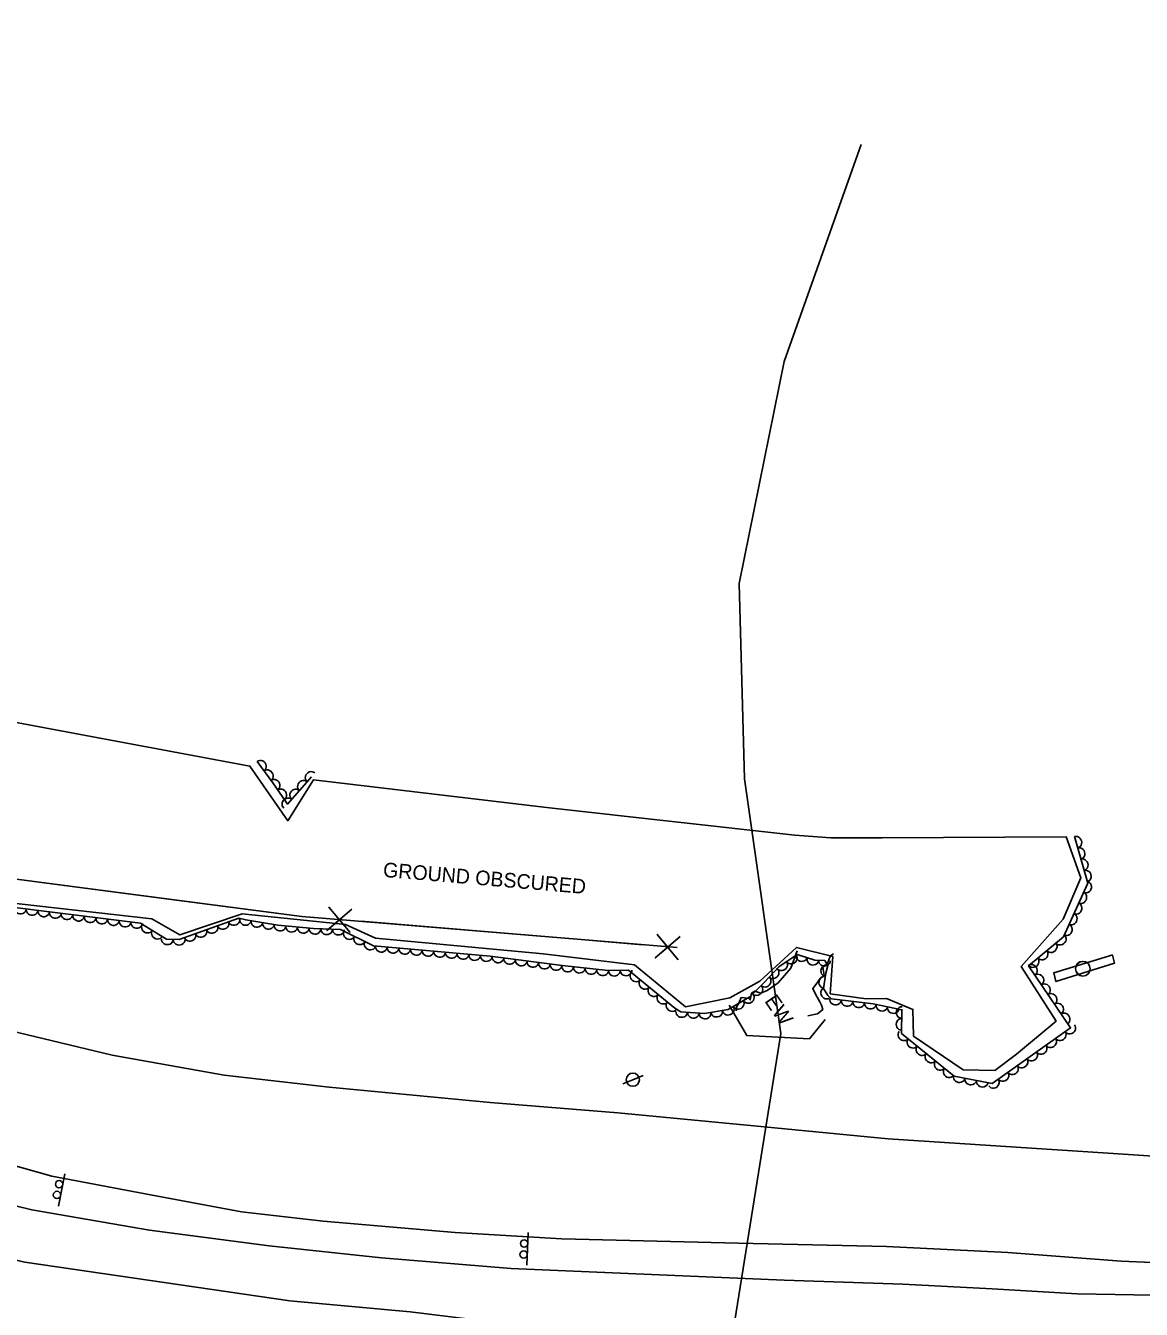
# Model space of a CAD drawing. Extents: x 1746719 to 1766531, y 631721 to 662391.
# Drawn here: x 1761818.8 to 1762199.7, y 638977.8 to 639416.3 of the extents above; entities that cross this region are included whole.
import ezdxf

# ---------------------------------------------------------------- set-up
doc = ezdxf.new("R2010")
doc.units = 0
for name, color, linetype in [('SURVEY - AERIAL SURVEY - Photo Control - Points - Elevations', 7, 'Continuous'), ('SURVEY - AERIAL SURVEY - Photo Control - Points - Locators', 7, 'Continuous'), ('SURVEY - AERIAL SURVEY - Photo Control with Text', 7, 'Continuous'), ('SURVEY - CENTERLINE - Existing Roads - Development', 7, 'Continuous'), ('SURVEY - CENTERLINE - Existing Roads Curve Text', 7, 'Continuous'), ('SURVEY - CENTERLINE - Existing Roads Text', 7, 'Continuous'), ('SURVEY - CENTERLINE - Preliminary - Development', 7, 'Continuous'), ('SURVEY - CONTROL - Grid', 7, 'Continuous'), ('SURVEY - CONTROL - Points - Locators', 7, 'Continuous')]:
    doc.layers.add(name, color=color, linetype=linetype)

msp = doc.modelspace()

# ---------------------------------------------------------------- linework, layer by layer
at = {"layer": 'SURVEY - AERIAL SURVEY - Photo Control - Points - Elevations'}
for points in [[(1762261.08, 639027.06), (1762233.34, 639028.14), (1762181.48, 639031.56), (1762113.28, 639036.02), (1762067.41, 639040.43), (1762020.97, 639044.87), (1761977.38, 639048.35), (1761922.36, 639053.65), (1761886.58, 639057.73), (1761848.26, 639064.58), (1761813.22, 639072.98), (1761793.14, 639078.56), (1761774.07, 639086), (1761753.7, 639095.14), (1761734.87, 639105.33), (1761713.99, 639118.1), (1761694.82, 639131.16), (1761676.63, 639144.46), (1761659.86, 639158.72), (1761634.88, 639183.87), (1761613.94, 639210.23)], [(1762224.67, 638992.89), (1762192.9, 638994.18), (1762154.14, 638997.18), (1762112.69, 638999.16), (1762062.15, 639000.35), (1762001.83, 639001.82), (1761965.46, 639004.02), (1761920.31, 639007.88), (1761892.51, 639011.1), (1761861.4, 639016.81), (1761827.66, 639023.26), (1761803.02, 639030.18), (1761777.45, 639038.01), (1761755.32, 639046.63), (1761734.71, 639055.73), (1761714.76, 639065.84), (1761701.3, 639074.56), (1761685.53, 639086.04), (1761666.8, 639103.09), (1761633.96, 639133.17)], [(1761761.43, 638889.76), (1761732.82, 638943.46), (1761689.11, 639018.83), (1761678.54, 639035.23), (1761673.98, 639043.58), (1761670.36, 639051.32), (1761676.06, 639046.25), (1761687.5, 639039.11), (1761708.75, 639029.22), (1761743.69, 639014.09), (1761782.73, 639002.07), (1761818.46, 638993.91), (1761909.01, 638980.63), (1761950.02, 638976.86), (1761999.13, 638970.87), (1762027.18, 638966.51)], [(1762203.68, 638982.54), (1762177.88, 638983.07), (1762148.83, 638984.76), (1762118.36, 638986.3), (1762077.82, 638987.71), (1761984.52, 638991.75), (1761940.26, 638995.29), (1761901.87, 638999.4), (1761861.06, 639004.76), (1761820.92, 639011.75), (1761785.92, 639020.26)]]:
    msp.add_lwpolyline(points, dxfattribs=at)
at = {"layer": 'SURVEY - AERIAL SURVEY - Photo Control - Points - Locators'}
for points in [[(1761795.41, 639181.95), (1761895.34, 639163.31), (1761908.26, 639144.67), (1761917.1, 639158.64), (1761997.65, 639149.1), (1762081.47, 639139.69), (1762093.68, 639138.77), (1762111.28, 639138.76), (1762174.12, 639139.16), (1762179.08, 639125.1), (1762173.02, 639110.99), (1762158.72, 639094.91), (1762170.62, 639076.22), (1762157.1, 639064.93), (1762149.77, 639059.28), (1762138.91, 639059.54), (1762121.97, 639071.12), (1762121.77, 639080.23), (1762112.7, 639083.92), (1762105.83, 639083.77)], [(1762105.83, 639083.77), (1762093.53, 639085.53), (1762094.45, 639098.25), (1762082.03, 639101.41), (1762069.45, 639089.89), (1762059.18, 639084.14), (1762044.09, 639081.12), (1762026.66, 639095.43), (1761995.47, 639099.24), (1761938.25, 639104.55), (1761928.02, 639109.23), (1761892.65, 639112.88), (1761871.42, 639105.64), (1761861.89, 639111.09), (1761810.55, 639116.93)]]:
    msp.add_lwpolyline(points, dxfattribs=at)
at = {"layer": 'SURVEY - AERIAL SURVEY - Photo Control with Text'}
for points in [[(1761897.82, 639164.92), (1761903.14, 639157.61), (1761907.51, 639151.3), (1761908.15, 639150.37), (1761916.36, 639159.67)], [(1762176.95, 639139.24), (1762181.43, 639123.33), (1762173.17, 639105.03), (1762161.22, 639095.13), (1762175.56, 639073.91), (1762148.79, 639054.9), (1762135.79, 639057.45), (1762117.87, 639072.03), (1762118.01, 639080.1), (1762108.14, 639082.13), (1762094, 639083.79), (1762092.71, 639084.93), (1762091.23, 639087.34), (1762092.01, 639092.63), (1762092.73, 639095.25), (1762091.65, 639096.87), (1762088.3, 639097.03), (1762082.19, 639099), (1762075.98, 639094.7), (1762070.93, 639089.35), (1762066.04, 639084.47), (1762058.71, 639080.18), (1762050.56, 639078.79), (1762042.51, 639079.4), (1762040.41, 639080.66), (1762024.67, 639093.59), (1762017.68, 639093.44), (1762001.92, 639095.15), (1761977.37, 639098.38), (1761937.51, 639101.89), (1761926.27, 639107.48), (1761917.01, 639107.82), (1761904.93, 639108.94), (1761893.94, 639110.8), (1761891.52, 639111.41), (1761871.22, 639104.05), (1761866.91, 639104.21), (1761859.22, 639108.86), (1761858.03, 639109.63), (1761808.55, 639115.77)]]:
    msp.add_lwpolyline(points, dxfattribs=at)
for centre, major_axis in [((1761899, 639163.31), (1.18, -1.62)), ((1761901.35, 639160.07), (1.18, -1.62)), ((1761916.19, 639159.48), (1.32, 1.5)), ((1761903.68, 639156.82), (1.14, -1.64)), ((1761913.55, 639156.48), (1.32, 1.5)), ((1761905.96, 639153.53), (1.14, -1.64)), ((1761908.25, 639150.48), (1.32, 1.5)), ((1761910.9, 639153.48), (1.32, 1.5)), ((1762177.49, 639137.31), (0.54, -1.93)), ((1762178.58, 639133.46), (0.54, -1.93)), ((1762179.66, 639129.61), (0.54, -1.93)), ((1762180.74, 639125.76), (0.54, -1.93)), ((1762180.82, 639121.98), (-0.82, -1.82)), ((1762179.18, 639118.34), (-0.82, -1.82)), ((1761816.98, 639114.72), (-1.98, 0.25)), ((1761820.95, 639114.23), (-1.98, 0.25)), ((1761824.92, 639113.74), (-1.98, 0.25)), ((1761828.89, 639113.24), (-1.98, 0.25)), ((1762177.53, 639114.69), (-0.82, -1.82)), ((1761832.86, 639112.75), (-1.98, 0.25)), ((1761836.83, 639112.26), (-1.98, 0.25)), ((1761840.8, 639111.77), (-1.98, 0.25)), ((1761844.77, 639111.27), (-1.98, 0.25)), ((1761848.74, 639110.78), (-1.98, 0.25)), ((1761852.71, 639110.29), (-1.98, 0.25)), ((1761856.68, 639109.79), (-1.98, 0.25)), ((1761860.27, 639108.22), (-1.71, 1.03)), ((1761882.43, 639108.12), (-1.88, -0.68)), ((1761886.19, 639109.48), (-1.88, -0.68)), ((1761889.95, 639110.84), (-1.88, -0.68)), ((1761893.78, 639110.84), (-1.94, 0.49)), ((1761897.72, 639110.16), (-1.97, 0.33)), ((1761901.67, 639109.49), (-1.97, 0.33)), ((1761905.62, 639108.88), (-1.99, 0.19)), ((1761909.6, 639108.51), (-1.99, 0.19)), ((1762174.24, 639107.4), (-0.82, -1.82)), ((1762175.89, 639111.05), (-0.82, -1.82)), ((1761863.69, 639106.16), (-1.71, 1.03)), ((1761867.15, 639104.21), (-2, 0.08)), ((1761874.91, 639105.39), (-1.88, -0.68)), ((1761878.67, 639106.75), (-1.88, -0.68)), ((1761913.59, 639108.14), (-1.99, 0.19)), ((1761917.57, 639107.8), (-2, 0.07)), ((1761921.57, 639107.65), (-2, 0.07)), ((1761925.56, 639107.51), (-2, 0.07)), ((1761929.22, 639106.02), (-1.79, 0.89)), ((1761932.8, 639104.23), (-1.79, 0.89)), ((1762172.1, 639104.14), (-1.54, -1.28)), ((1761871.15, 639104.05), (-2, 0.08)), ((1761936.38, 639102.45), (-1.79, 0.89)), ((1761940.24, 639101.65), (-1.99, 0.18)), ((1761944.22, 639101.3), (-1.99, 0.18)), ((1761948.21, 639100.95), (-1.99, 0.18)), ((1761952.19, 639100.6), (-1.99, 0.18)), ((1761956.18, 639100.25), (-1.99, 0.18)), ((1761960.16, 639099.89), (-1.99, 0.18)), ((1762165.93, 639099.04), (-1.54, -1.28)), ((1762169.02, 639101.59), (-1.54, -1.28)), ((1761964.15, 639099.54), (-1.99, 0.18)), ((1761968.13, 639099.19), (-1.99, 0.18)), ((1761972.12, 639098.84), (-1.99, 0.18)), ((1761976.1, 639098.49), (-1.99, 0.18)), ((1761980.07, 639098.02), (-1.98, 0.26)), ((1761984.04, 639097.5), (-1.98, 0.26)), ((1761988, 639096.98), (-1.98, 0.26)), ((1761991.97, 639096.46), (-1.98, 0.26)), ((1761995.94, 639095.94), (-1.98, 0.26)), ((1761999.9, 639095.42), (-1.98, 0.26)), ((1762076.97, 639095.39), (-1.64, -1.14)), ((1762080.26, 639097.67), (-1.64, -1.14)), ((1762083.76, 639098.49), (-1.9, 0.62)), ((1762087.57, 639097.26), (-1.9, 0.62)), ((1762091.53, 639096.88), (-2, 0.09)), ((1762092.22, 639093.39), (0.53, 1.93)), ((1762162.27, 639093.58), (1.12, -1.66)), ((1762162.85, 639096.48), (-1.54, -1.28)), ((1762003.87, 639094.94), (-1.99, 0.22)), ((1762007.85, 639094.51), (-1.99, 0.22)), ((1762011.83, 639094.08), (-1.99, 0.22)), ((1762015.8, 639093.64), (-1.99, 0.22)), ((1762019.79, 639093.49), (-2, -0.04)), ((1762023.79, 639093.57), (-2, -0.04)), ((1762027.08, 639091.61), (-1.55, 1.27)), ((1762071.32, 639089.76), (-1.37, -1.45)), ((1762074.06, 639092.67), (-1.37, -1.45)), ((1762091.54, 639089.46), (0.29, 1.98)), ((1762164.51, 639090.26), (1.12, -1.66)), ((1762030.17, 639089.07), (-1.55, 1.27)), ((1762033.26, 639086.53), (-1.55, 1.27)), ((1762068.5, 639086.92), (-1.42, -1.41)), ((1762092.21, 639085.76), (-1.05, 1.7)), ((1762166.75, 639086.95), (1.12, -1.66)), ((1762036.36, 639083.99), (-1.55, 1.27)), ((1762039.45, 639081.45), (-1.55, 1.27)), ((1762062.13, 639082.18), (-1.73, -1.01)), ((1762065.58, 639084.2), (-1.73, -1.01)), ((1762095.31, 639083.64), (-1.99, 0.23)), ((1762099.28, 639083.17), (-1.99, 0.23)), ((1762103.25, 639082.7), (-1.99, 0.23)), ((1762107.22, 639082.23), (-1.99, 0.23)), ((1762168.99, 639083.63), (1.12, -1.66)), ((1762171.23, 639080.32), (1.12, -1.66)), ((1762042.82, 639079.38), (-1.99, 0.15)), ((1762046.8, 639079.08), (-1.99, 0.15)), ((1762050.79, 639078.83), (-1.97, -0.34)), ((1762054.73, 639079.5), (-1.97, -0.34)), ((1762058.67, 639080.17), (-1.97, -0.34)), ((1762111.16, 639081.51), (-1.96, 0.4)), ((1762115.07, 639080.71), (-1.96, 0.4)), ((1762117.99, 639079.1), (0.04, 2)), ((1762173.47, 639077), (1.12, -1.66)), ((1762117.92, 639075.1), (0.04, 2)), ((1762175.35, 639073.75), (-1.63, -1.16)), ((1762118.59, 639071.45), (-1.55, 1.26)), ((1762121.69, 639068.92), (-1.55, 1.26)), ((1762168.83, 639069.12), (-1.63, -1.16)), ((1762172.09, 639071.44), (-1.63, -1.16)), ((1762124.79, 639066.4), (-1.55, 1.26)), ((1762127.89, 639063.87), (-1.55, 1.26)), ((1762162.31, 639064.49), (-1.63, -1.16)), ((1762165.57, 639066.81), (-1.63, -1.16)), ((1762131, 639061.35), (-1.55, 1.26)), ((1762155.78, 639059.86), (-1.63, -1.16)), ((1762159.04, 639062.18), (-1.63, -1.16)), ((1762134.1, 639058.83), (-1.55, 1.26)), ((1762137.58, 639057.1), (-1.96, 0.39)), ((1762141.5, 639056.33), (-1.96, 0.39)), ((1762149.26, 639055.23), (-1.63, -1.16)), ((1762152.52, 639057.55), (-1.63, -1.16)), ((1762145.43, 639055.56), (-1.96, 0.39))]:
    msp.add_ellipse(centre, major_axis=major_axis, ratio=0.940188, start_param=0, end_param=3.141593, dxfattribs=at)
at = {"layer": 'SURVEY - CENTERLINE - Existing Roads - Development'}
for q in [(1762022.66, 639054.74), (1762029.58, 639057.64)]:
    msp.add_line((1762026.12, 639056.19), q, dxfattribs=at)
msp.add_circle((1762026.12, 639056.19), 2.25, dxfattribs=at)
at = {"layer": 'SURVEY - CENTERLINE - Existing Roads Curve Text'}
for points in [[(1761265.97, 639858.91), (1761307.06, 639795.97), (1761356.57, 639717.75), (1761380.9, 639679.88), (1761379.97, 639625.73), (1761424.41, 639557.01), (1761485.02, 639462.73), (1761530.98, 639389.15), (1761579.28, 639309.27), (1761623.78, 639236.15), (1761657.08, 639181.54), (1761712.91, 639157.86), (1761781.37, 639128.88), (1761814.76, 639124.81), (1761913.04, 639111.99), (1762009.85, 639103.93), (1762041.29, 639101.31)], [(1761821.69, 639123.91), (1761867.7, 639117.9)], [(1761867.7, 639117.9), (1761913.04, 639111.99), (1761917.3, 639111.63)], [(1761930.18, 639114.47), (1761921.64, 639107.16), (1761925.96, 639110.81), (1761922.31, 639115.13), (1761929.52, 639106.5)], [(1761933.34, 639110.3), (1761979.58, 639106.45)], [(1761979.58, 639106.45), (1762009.85, 639103.93), (1762029.41, 639102.3)], [(1762042.29, 639105.14), (1762033.76, 639097.82), (1762038.07, 639101.48), (1762034.42, 639105.8), (1762041.63, 639097.17)]]:
    msp.add_lwpolyline(points, dxfattribs=at)
at = {"layer": 'SURVEY - CENTERLINE - Existing Roads Text'}
msp.add_lwpolyline([(1762059.05, 639081.6), (1762065, 639071.29), (1762086.42, 639070.18), (1762091.83, 639076.74)], dxfattribs=at)
at = {"layer": 'SURVEY - CONTROL - Grid'}
for p, q in [((1762179.77, 639094.08), (1762179.77, 639094.08)), ((1762179.77, 639094.08), (1762179.77, 639094.08)), ((1761832.09, 639024.02), (1761829.96, 639013.03)), ((1761990.38, 639003.99), (1761989.88, 638992.8))]:
    msp.add_line(p, q, dxfattribs=at)
for points in [[(1762189.85, 639098.76), (1762190.56, 639096), (1762170.57, 639089.72), (1762169.84, 639092.73), (1762190.03, 639098.87)], [(1762189.85, 639098.76), (1762190.56, 639096), (1762170.57, 639089.73), (1762169.84, 639092.73), (1762190.03, 639098.87)]]:
    msp.add_lwpolyline(points, dxfattribs=at)
for centre, radius in [((1762179.77, 639094.1), 2.5), ((1762179.78, 639094.1), 2.5), ((1761830.16, 639020.5), 1.25), ((1761829.45, 639016.82), 1.25), ((1761988.99, 639000.23), 1.25), ((1761988.82, 638996.48), 1.25)]:
    msp.add_circle(centre, radius, dxfattribs=at)
at = {"layer": 'SURVEY - CONTROL - Points - Locators'}
for points in [[(1761891.07, 637793.83), (1761899.22, 637993.48), (1761897.33, 638030.68), (1761892.33, 638078.24), (1761896.45, 638096.58), (1761907.7, 638114.75), (1761933.23, 638143.98), (1762059.54, 638364.83), (1762056.48, 638440.73), (1762027.97, 638570.7), (1762020.66, 638639.38), (1762017.5, 638702.57), (1762076.59, 639071.99), (1762064.24, 639158.94), (1762062.45, 639225.72), (1762077.73, 639301.51), (1762104.06, 639375.67)], [(1762082.19, 639100.2), (1762080, 639094.26), (1762075.72, 639089.32), (1762071.94, 639086.7), (1762069.8, 639085.75), (1762067.77, 639086.47), (1762066.99, 639085.93), (1762066.59, 639085.74), (1762066.18, 639083.45), (1762065.68, 639083.88), (1762064.2, 639084.11), (1762063.14, 639084.28), (1762062.28, 639082.35), (1762061.55, 639080.97), (1762061.43, 639080.03), (1762061.37, 639079.68)], [(1762085.91, 639077.96), (1762089.21, 639078.73), (1762091, 639080.23), (1762090.56, 639081.7), (1762089.94, 639082.84), (1762088.59, 639085.14), (1762087.56, 639087.32), (1762088.68, 639088.8), (1762090.06, 639090.76), (1762091.46, 639091.94), (1762090.99, 639094.59), (1762092.61, 639095.89), (1762093.11, 639097.47), (1762093.73, 639098.64), (1762094.57, 639099.22)]]:
    msp.add_lwpolyline(points, dxfattribs=at)

# ---------------------------------------------------------------- texts
at = {"layer": 'SURVEY - AERIAL SURVEY - Photo Control - Points - Locators'}
msp.add_text('GROUND OBSCURED', height=5, rotation=355.1584, dxfattribs=at).set_placement((1761940.66, 639125.5))
at = {"layer": 'SURVEY - CENTERLINE - Preliminary - Development'}
msp.add_text('EW', height=5, rotation=304.7026, dxfattribs=at).set_placement((1762070.88, 639083.05))

doc.saveas('drawing.dxf')
